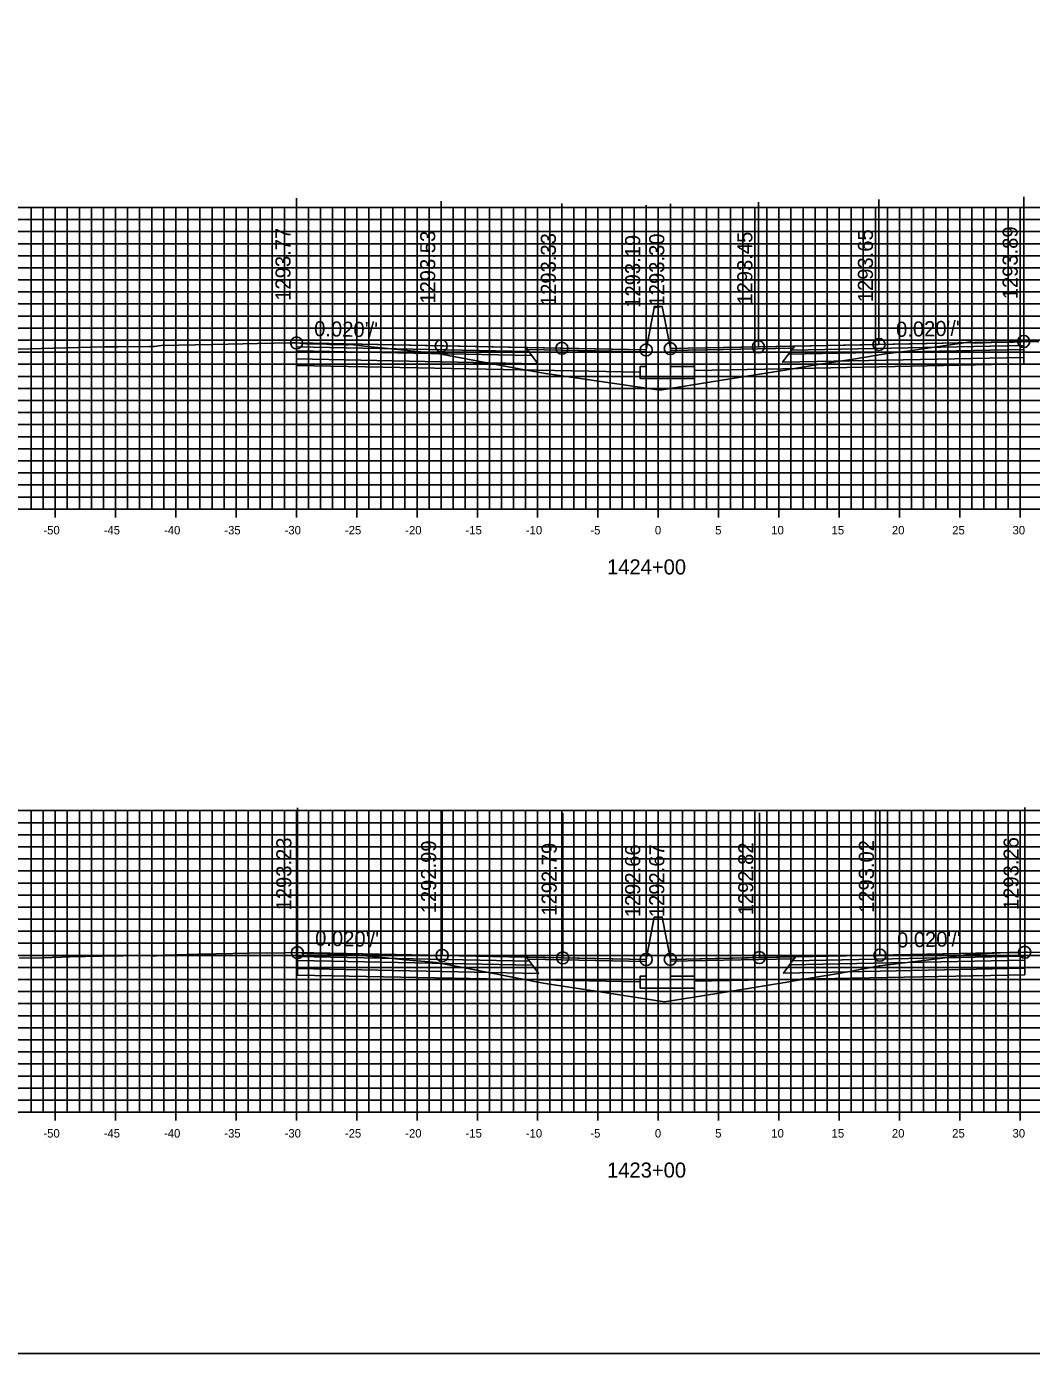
# Model space of a CAD drawing. Extents: x 674939 to 678919, y 750652 to 765176.
# Drawn here: x 678696.2 to 678779.5, y 757822.6 to 757932.6 of the extents above; entities that cross this region are included whole.
import ezdxf

# ---------------------------------------------------------------- set-up
doc = ezdxf.new("R2010")
doc.units = 0
for name, color, linetype in [('R_Alt Surface', 7, 'Continuous'), ('R_Axis', 7, 'Continuous'), ('R_Axis Annot', 7, 'Continuous'), ('R_Exist Surface', 7, 'Continuous'), ('R_Fin Surface', 7, 'Continuous'), ('R_Grid', 7, 'Continuous'), ('R_No Plot', 7, 'Continuous'), ('R_Proposed Road', 7, 'Continuous'), ('R_Xsect Elev', 7, 'Continuous'), ('R_Xsect Slope', 7, 'Continuous')]:
    doc.layers.add(name, color=color, linetype=linetype)

msp = doc.modelspace()

# ---------------------------------------------------------------- linework, layer by layer
for points in [[(678748.2, 757909.24), (678747.53, 757905.74)], [(678748.86, 757909.35), (678748.86, 757909.35), (678748.2, 757909.35), (678748.2, 757909.24)], [(678748.86, 757909.35), (678749.53, 757905.85)], [(678748.2, 757858.71), (678747.53, 757855.21)], [(678748.86, 757858.72), (678748.86, 757858.72), (678748.2, 757858.72), (678748.2, 757858.71)], [(678748.86, 757858.72), (678749.53, 757855.22)]]:
    msp.add_lwpolyline(points)
at = {"layer": 'R_Alt Surface'}
for points in [[(678718.54, 757905.99), (678718.54, 757905.66), (678738.04, 757905.27), (678737.79, 757905.61)], [(678718.54, 757905.66), (678718.54, 757905), (678738.54, 757904.6), (678738.04, 757905.27)], [(678778.83, 757905.78), (678778.83, 757905.12), (678758.83, 757904.72), (678759.33, 757905.39)], [(678778.83, 757906.11), (678778.83, 757905.78), (678759.33, 757905.39), (678759.58, 757905.72)], [(678718.61, 757855.45), (678718.61, 757855.12), (678738.11, 757854.73), (678737.86, 757855.07)], [(678718.61, 757855.12), (678718.61, 757854.46), (678738.61, 757854.06), (678738.11, 757854.73)], [(678778.91, 757855.15), (678778.91, 757854.49), (678758.91, 757854.09), (678759.41, 757854.76)], [(678778.91, 757855.48), (678778.91, 757855.15), (678759.41, 757854.76), (678759.66, 757855.1)]]:
    msp.add_lwpolyline(points, close=True, dxfattribs=at)
for points in [[(678718.54, 757905), (678718.54, 757904.46), (678738.54, 757904.06), (678747.03, 757903.89)], [(678778.83, 757905.12), (678778.83, 757904.58), (678758.83, 757904.18), (678751.53, 757904.03)], [(678718.61, 757854.46), (678718.61, 757853.92), (678738.61, 757853.52), (678747.03, 757853.36)], [(678778.91, 757854.49), (678778.91, 757853.95), (678758.91, 757853.55), (678751.53, 757853.4)]]:
    msp.add_lwpolyline(points, dxfattribs=at)
at = {"layer": 'R_Axis'}
for p, q in [((678598.53, 757892.55), (678898.53, 757892.55)), ((678698.53, 757891.85), (678698.53, 757893.25)), ((678703.53, 757891.85), (678703.53, 757893.25)), ((678708.53, 757891.85), (678708.53, 757893.25)), ((678713.53, 757891.85), (678713.53, 757893.25)), ((678718.53, 757891.85), (678718.53, 757893.25)), ((678723.53, 757891.85), (678723.53, 757893.25)), ((678728.53, 757891.85), (678728.53, 757893.25)), ((678733.53, 757891.85), (678733.53, 757893.25)), ((678738.53, 757891.85), (678738.53, 757893.25)), ((678743.53, 757891.85), (678743.53, 757893.25)), ((678748.53, 757891.85), (678748.53, 757893.25)), ((678753.53, 757891.85), (678753.53, 757893.25)), ((678758.53, 757891.85), (678758.53, 757893.25)), ((678763.53, 757891.85), (678763.53, 757893.25)), ((678768.53, 757891.85), (678768.53, 757893.25)), ((678773.53, 757891.85), (678773.53, 757893.25)), ((678778.53, 757891.85), (678778.53, 757893.25)), ((678698.53, 757841.85), (678698.53, 757843.25)), ((678703.53, 757841.85), (678703.53, 757843.25)), ((678708.53, 757841.85), (678708.53, 757843.25)), ((678713.53, 757841.85), (678713.53, 757843.25)), ((678718.53, 757841.85), (678718.53, 757843.25)), ((678723.53, 757841.85), (678723.53, 757843.25)), ((678728.53, 757841.85), (678728.53, 757843.25)), ((678733.53, 757841.85), (678733.53, 757843.25)), ((678738.53, 757841.85), (678738.53, 757843.25)), ((678743.53, 757841.85), (678743.53, 757843.25)), ((678748.53, 757841.85), (678748.53, 757843.25)), ((678753.53, 757841.85), (678753.53, 757843.25)), ((678758.53, 757841.85), (678758.53, 757843.25)), ((678763.53, 757841.85), (678763.53, 757843.25)), ((678768.53, 757841.85), (678768.53, 757843.25)), ((678773.53, 757841.85), (678773.53, 757843.25)), ((678778.53, 757841.85), (678778.53, 757843.25)), ((678598.53, 757842.55), (678898.53, 757842.55))]:
    msp.add_line(p, q, dxfattribs=at)
at = {"layer": 'R_Exist Surface'}
for points in [[(678695.45, 757905.81), (678697.36, 757905.87), (678702.49, 757905.99), (678703.75, 757906.01), (678706.32, 757906.04), (678706.46, 757906.02), (678706.52, 757906.02), (678706.75, 757906.04), (678707.32, 757906.1), (678710.16, 757906.16), (678712.88, 757906.22), (678715.29, 757906.27), (678718, 757906.32), (678718.52, 757906.32), (678718.52, 757906.32), (678718.54, 757906.32), (678719.09, 757906.27), (678719.37, 757906.25), (678720.37, 757906.25), (678720.72, 757906.25), (678721.29, 757906.2), (678721.81, 757906.18), (678722.66, 757906.16), (678722.77, 757906.17), (678723.02, 757906.18), (678723.05, 757906.19), (678724.16, 757906.06), (678730.22, 757905.45), (678737, 757904.17), (678739.18, 757903.78), (678744.15, 757903.07), (678748.67, 757902.41), (678755.34, 757903.48), (678759.01, 757904.07), (678761.78, 757904.53), (678764.88, 757905.01), (678767.34, 757905.43), (678769.41, 757905.68), (678771.2, 757905.95), (678774.44, 757906.41), (678774.55, 757906.37), (678774.66, 757906.32), (678774.87, 757906.31), (678775.5, 757906.34), (678776.82, 757906.38), (678777.98, 757906.39), (678778.46, 757906.4), (678778.64, 757906.42), (678778.83, 757906.44), (678778.85, 757906.44), (678778.95, 757906.44), (678780.08, 757906.41)], [(678695.56, 757855.32), (678697.56, 757855.36), (678699.74, 757855.42), (678702.36, 757855.48), (678704.17, 757855.5), (678706.29, 757855.53), (678706.54, 757855.51), (678706.69, 757855.5), (678706.91, 757855.52), (678707.66, 757855.58), (678710.4, 757855.64), (678713.27, 757855.7), (678716.01, 757855.75), (678716.13, 757855.74), (678717.49, 757855.76), (678718.49, 757855.8), (678718.61, 757855.78), (678718.62, 757855.78), (678718.92, 757855.76), (678719.41, 757855.72), (678719.72, 757855.71), (678720.34, 757855.71), (678721.1, 757855.68), (678722.46, 757855.62), (678722.82, 757855.61), (678723.18, 757855.63), (678727.56, 757855.19), (678728.85, 757855.08), (678730.14, 757854.96), (678731.43, 757854.71), (678733.19, 757854.37), (678739, 757853.25), (678744.43, 757852.42), (678749.06, 757851.7), (678754.96, 757852.65), (678759.03, 757853.3), (678761.13, 757853.66), (678763.65, 757854.09), (678766.89, 757854.69), (678772.1, 757855.33), (678774.6, 757855.68), (678774.63, 757855.68), (678774.73, 757855.65), (678776.35, 757855.73), (678776.89, 757855.75), (678778.18, 757855.78), (678778.45, 757855.79), (678778.91, 757855.81), (678778.95, 757855.81), (678779.13, 757855.82), (678781.27, 757855.79)]]:
    msp.add_lwpolyline(points, dxfattribs=at)
at = {"layer": 'R_Fin Surface'}
for points in [[(678718.54, 757906.32), (678730.54, 757906.08), (678737.54, 757905.94), (678740.54, 757905.88), (678747.53, 757905.74), (678748.2, 757909.24), (678748.86, 757909.35), (678749.53, 757905.85), (678756.83, 757906), (678759.83, 757906.06), (678766.83, 757906.2), (678778.83, 757906.44)], [(678747.53, 757905.74), (678740.54, 757905.88), (678730.54, 757906.08), (678718.54, 757906.32)], [(678778.83, 757906.44), (678766.83, 757906.2), (678756.83, 757906), (678749.53, 757905.85)], [(678718.61, 757855.78), (678730.61, 757855.54), (678737.61, 757855.4), (678740.61, 757855.34), (678747.53, 757855.21), (678748.2, 757858.71), (678748.86, 757858.72), (678749.53, 757855.22), (678756.91, 757855.37), (678759.91, 757855.43), (678766.91, 757855.57), (678778.91, 757855.81)], [(678747.53, 757855.21), (678740.61, 757855.34), (678730.61, 757855.54), (678718.61, 757855.78)], [(678778.91, 757855.81), (678766.91, 757855.57), (678756.91, 757855.37), (678749.53, 757855.22)]]:
    msp.add_lwpolyline(points, dxfattribs=at)
for points in [[(678718.54, 757906.32), (678718.54, 757905.99), (678737.79, 757905.61), (678737.54, 757905.94)], [(678737.54, 757905.94), (678747.53, 757905.74), (678747.54, 757905.58), (678737.66, 757905.78)], [(678759.71, 757905.9), (678749.53, 757905.69), (678749.53, 757905.85), (678759.83, 757906.06)], [(678778.83, 757906.44), (678778.83, 757906.11), (678759.58, 757905.72), (678759.83, 757906.06)], [(678718.61, 757855.78), (678718.61, 757855.45), (678737.86, 757855.07), (678737.61, 757855.4)], [(678737.61, 757855.4), (678747.53, 757855.21), (678747.54, 757855.05), (678737.73, 757855.24)], [(678759.79, 757855.27), (678749.53, 757855.07), (678749.53, 757855.22), (678759.91, 757855.43)], [(678778.91, 757855.81), (678778.91, 757855.48), (678759.66, 757855.1), (678759.91, 757855.43)]]:
    msp.add_lwpolyline(points, close=True, dxfattribs=at)
at = {"layer": 'R_Grid'}
for p, q in [((678598.53, 757917.55), (678898.53, 757917.55)), ((678598.53, 757916.55), (678898.53, 757916.55)), ((678696.53, 757892.55), (678696.53, 757917.55)), ((678697.53, 757892.55), (678697.53, 757917.55)), ((678698.53, 757892.55), (678698.53, 757917.55)), ((678699.53, 757892.55), (678699.53, 757917.55)), ((678700.53, 757892.55), (678700.53, 757917.55)), ((678701.53, 757892.55), (678701.53, 757917.55)), ((678702.53, 757892.55), (678702.53, 757917.55)), ((678703.53, 757892.55), (678703.53, 757917.55)), ((678704.53, 757892.55), (678704.53, 757917.55)), ((678705.53, 757892.55), (678705.53, 757917.55)), ((678706.53, 757892.55), (678706.53, 757917.55)), ((678707.53, 757892.55), (678707.53, 757917.55)), ((678708.53, 757892.55), (678708.53, 757917.55)), ((678709.53, 757892.55), (678709.53, 757917.55)), ((678710.53, 757892.55), (678710.53, 757917.55)), ((678711.53, 757892.55), (678711.53, 757917.55)), ((678712.53, 757892.55), (678712.53, 757917.55)), ((678713.53, 757892.55), (678713.53, 757917.55)), ((678714.53, 757892.55), (678714.53, 757917.55)), ((678715.53, 757892.55), (678715.53, 757917.55)), ((678716.53, 757892.55), (678716.53, 757917.55)), ((678717.53, 757892.55), (678717.53, 757917.55)), ((678718.53, 757892.55), (678718.53, 757917.55)), ((678719.53, 757892.55), (678719.53, 757917.55)), ((678720.53, 757892.55), (678720.53, 757917.55)), ((678721.53, 757892.55), (678721.53, 757917.55)), ((678722.53, 757892.55), (678722.53, 757917.55)), ((678723.53, 757892.55), (678723.53, 757917.55)), ((678724.53, 757892.55), (678724.53, 757917.55)), ((678725.53, 757892.55), (678725.53, 757917.55)), ((678726.53, 757892.55), (678726.53, 757917.55)), ((678727.53, 757892.55), (678727.53, 757917.55)), ((678728.53, 757892.55), (678728.53, 757917.55)), ((678729.53, 757892.55), (678729.53, 757917.55)), ((678730.53, 757892.55), (678730.53, 757917.55)), ((678731.53, 757892.55), (678731.53, 757917.55)), ((678732.53, 757892.55), (678732.53, 757917.55)), ((678733.53, 757892.55), (678733.53, 757917.55)), ((678734.53, 757892.55), (678734.53, 757917.55)), ((678735.53, 757892.55), (678735.53, 757917.55)), ((678736.53, 757892.55), (678736.53, 757917.55)), ((678737.53, 757892.55), (678737.53, 757917.55)), ((678738.53, 757892.55), (678738.53, 757917.55)), ((678739.53, 757892.55), (678739.53, 757917.55)), ((678740.53, 757892.55), (678740.53, 757917.55)), ((678741.53, 757892.55), (678741.53, 757917.55)), ((678742.53, 757892.55), (678742.53, 757917.55)), ((678743.53, 757892.55), (678743.53, 757917.55)), ((678744.53, 757892.55), (678744.53, 757917.55)), ((678745.53, 757892.55), (678745.53, 757917.55)), ((678746.53, 757892.55), (678746.53, 757917.55)), ((678747.53, 757892.55), (678747.53, 757917.55)), ((678748.53, 757892.55), (678748.53, 757917.55)), ((678749.53, 757892.55), (678749.53, 757917.55)), ((678750.53, 757892.55), (678750.53, 757917.55)), ((678751.53, 757892.55), (678751.53, 757917.55)), ((678752.53, 757892.55), (678752.53, 757917.55)), ((678753.53, 757892.55), (678753.53, 757917.55)), ((678754.53, 757892.55), (678754.53, 757917.55)), ((678755.53, 757892.55), (678755.53, 757917.55)), ((678756.53, 757892.55), (678756.53, 757917.55)), ((678757.53, 757892.55), (678757.53, 757917.55)), ((678758.53, 757892.55), (678758.53, 757917.55)), ((678759.53, 757892.55), (678759.53, 757917.55)), ((678760.53, 757892.55), (678760.53, 757917.55)), ((678761.53, 757892.55), (678761.53, 757917.55)), ((678762.53, 757892.55), (678762.53, 757917.55)), ((678763.53, 757892.55), (678763.53, 757917.55)), ((678764.53, 757892.55), (678764.53, 757917.55)), ((678765.53, 757892.55), (678765.53, 757917.55)), ((678766.53, 757892.55), (678766.53, 757917.55)), ((678767.53, 757892.55), (678767.53, 757917.55)), ((678768.53, 757892.55), (678768.53, 757917.55)), ((678769.53, 757892.55), (678769.53, 757917.55)), ((678770.53, 757892.55), (678770.53, 757917.55)), ((678771.53, 757892.55), (678771.53, 757917.55)), ((678772.53, 757892.55), (678772.53, 757917.55)), ((678773.53, 757892.55), (678773.53, 757917.55)), ((678774.53, 757892.55), (678774.53, 757917.55)), ((678775.53, 757892.55), (678775.53, 757917.55)), ((678776.53, 757892.55), (678776.53, 757917.55)), ((678777.53, 757892.55), (678777.53, 757917.55)), ((678778.53, 757892.55), (678778.53, 757917.55)), ((678598.53, 757915.55), (678898.53, 757915.55)), ((678598.53, 757914.55), (678898.53, 757914.55)), ((678598.53, 757913.55), (678898.53, 757913.55)), ((678598.53, 757912.55), (678898.53, 757912.55)), ((678598.53, 757911.55), (678898.53, 757911.55)), ((678598.53, 757910.55), (678898.53, 757910.55)), ((678598.53, 757909.55), (678898.53, 757909.55)), ((678598.53, 757908.55), (678898.53, 757908.55)), ((678598.53, 757907.55), (678898.53, 757907.55)), ((678598.53, 757906.55), (678898.53, 757906.55)), ((678598.53, 757905.55), (678898.53, 757905.55)), ((678598.53, 757904.55), (678898.53, 757904.55)), ((678598.53, 757903.55), (678898.53, 757903.55)), ((678598.53, 757902.55), (678898.53, 757902.55)), ((678598.53, 757901.55), (678898.53, 757901.55)), ((678598.53, 757900.55), (678898.53, 757900.55)), ((678598.53, 757899.55), (678898.53, 757899.55)), ((678598.53, 757898.55), (678898.53, 757898.55)), ((678598.53, 757897.55), (678898.53, 757897.55)), ((678598.53, 757896.55), (678898.53, 757896.55)), ((678598.53, 757895.55), (678898.53, 757895.55)), ((678598.53, 757894.55), (678898.53, 757894.55)), ((678598.53, 757893.55), (678898.53, 757893.55)), ((678598.53, 757892.55), (678898.53, 757892.55)), ((678598.53, 757867.55), (678898.53, 757867.55)), ((678696.53, 757842.55), (678696.53, 757867.55)), ((678697.53, 757842.55), (678697.53, 757867.55)), ((678698.53, 757842.55), (678698.53, 757867.55)), ((678699.53, 757842.55), (678699.53, 757867.55)), ((678700.53, 757842.55), (678700.53, 757867.55)), ((678701.53, 757842.55), (678701.53, 757867.55)), ((678702.53, 757842.55), (678702.53, 757867.55)), ((678703.53, 757842.55), (678703.53, 757867.55)), ((678704.53, 757842.55), (678704.53, 757867.55)), ((678705.53, 757842.55), (678705.53, 757867.55)), ((678706.53, 757842.55), (678706.53, 757867.55)), ((678707.53, 757842.55), (678707.53, 757867.55)), ((678708.53, 757842.55), (678708.53, 757867.55)), ((678709.53, 757842.55), (678709.53, 757867.55)), ((678710.53, 757842.55), (678710.53, 757867.55)), ((678711.53, 757842.55), (678711.53, 757867.55)), ((678712.53, 757842.55), (678712.53, 757867.55)), ((678713.53, 757842.55), (678713.53, 757867.55)), ((678714.53, 757842.55), (678714.53, 757867.55)), ((678715.53, 757842.55), (678715.53, 757867.55)), ((678716.53, 757842.55), (678716.53, 757867.55)), ((678717.53, 757842.55), (678717.53, 757867.55)), ((678718.53, 757842.55), (678718.53, 757867.55)), ((678719.53, 757842.55), (678719.53, 757867.55)), ((678720.53, 757842.55), (678720.53, 757867.55)), ((678721.53, 757842.55), (678721.53, 757867.55)), ((678722.53, 757842.55), (678722.53, 757867.55)), ((678723.53, 757842.55), (678723.53, 757867.55)), ((678724.53, 757842.55), (678724.53, 757867.55)), ((678725.53, 757842.55), (678725.53, 757867.55)), ((678726.53, 757842.55), (678726.53, 757867.55)), ((678727.53, 757842.55), (678727.53, 757867.55)), ((678728.53, 757842.55), (678728.53, 757867.55)), ((678729.53, 757842.55), (678729.53, 757867.55)), ((678730.53, 757842.55), (678730.53, 757867.55)), ((678731.53, 757842.55), (678731.53, 757867.55)), ((678732.53, 757842.55), (678732.53, 757867.55)), ((678733.53, 757842.55), (678733.53, 757867.55)), ((678734.53, 757842.55), (678734.53, 757867.55)), ((678735.53, 757842.55), (678735.53, 757867.55)), ((678736.53, 757842.55), (678736.53, 757867.55)), ((678737.53, 757842.55), (678737.53, 757867.55)), ((678738.53, 757842.55), (678738.53, 757867.55)), ((678739.53, 757842.55), (678739.53, 757867.55)), ((678740.53, 757842.55), (678740.53, 757867.55)), ((678741.53, 757842.55), (678741.53, 757867.55)), ((678742.53, 757842.55), (678742.53, 757867.55)), ((678743.53, 757842.55), (678743.53, 757867.55)), ((678744.53, 757842.55), (678744.53, 757867.55)), ((678745.53, 757842.55), (678745.53, 757867.55)), ((678746.53, 757842.55), (678746.53, 757867.55)), ((678747.53, 757842.55), (678747.53, 757867.55)), ((678748.53, 757842.55), (678748.53, 757867.55)), ((678749.53, 757842.55), (678749.53, 757867.55)), ((678750.53, 757842.55), (678750.53, 757867.55)), ((678751.53, 757842.55), (678751.53, 757867.55)), ((678752.53, 757842.55), (678752.53, 757867.55)), ((678753.53, 757842.55), (678753.53, 757867.55)), ((678754.53, 757842.55), (678754.53, 757867.55)), ((678755.53, 757842.55), (678755.53, 757867.55)), ((678756.53, 757842.55), (678756.53, 757867.55)), ((678757.53, 757842.55), (678757.53, 757867.55)), ((678758.53, 757842.55), (678758.53, 757867.55)), ((678759.53, 757842.55), (678759.53, 757867.55)), ((678760.53, 757842.55), (678760.53, 757867.55)), ((678761.53, 757842.55), (678761.53, 757867.55)), ((678762.53, 757842.55), (678762.53, 757867.55)), ((678763.53, 757842.55), (678763.53, 757867.55)), ((678764.53, 757842.55), (678764.53, 757867.55)), ((678765.53, 757842.55), (678765.53, 757867.55)), ((678766.53, 757842.55), (678766.53, 757867.55)), ((678767.53, 757842.55), (678767.53, 757867.55)), ((678768.53, 757842.55), (678768.53, 757867.55)), ((678769.53, 757842.55), (678769.53, 757867.55)), ((678770.53, 757842.55), (678770.53, 757867.55)), ((678771.53, 757842.55), (678771.53, 757867.55)), ((678772.53, 757842.55), (678772.53, 757867.55)), ((678773.53, 757842.55), (678773.53, 757867.55)), ((678774.53, 757842.55), (678774.53, 757867.55)), ((678775.53, 757842.55), (678775.53, 757867.55)), ((678776.53, 757842.55), (678776.53, 757867.55)), ((678777.53, 757842.55), (678777.53, 757867.55)), ((678778.53, 757842.55), (678778.53, 757867.55)), ((678598.53, 757866.55), (678898.53, 757866.55)), ((678598.53, 757865.55), (678898.53, 757865.55)), ((678598.53, 757864.55), (678898.53, 757864.55)), ((678598.53, 757863.55), (678898.53, 757863.55)), ((678598.53, 757862.55), (678898.53, 757862.55)), ((678598.53, 757861.55), (678898.53, 757861.55)), ((678598.53, 757860.55), (678898.53, 757860.55)), ((678598.53, 757859.55), (678898.53, 757859.55)), ((678598.53, 757858.55), (678898.53, 757858.55)), ((678598.53, 757857.55), (678898.53, 757857.55)), ((678598.53, 757856.55), (678898.53, 757856.55)), ((678598.53, 757855.55), (678898.53, 757855.55)), ((678598.53, 757854.55), (678898.53, 757854.55)), ((678598.53, 757853.55), (678898.53, 757853.55)), ((678598.53, 757852.55), (678898.53, 757852.55)), ((678598.53, 757851.55), (678898.53, 757851.55)), ((678598.53, 757850.55), (678898.53, 757850.55)), ((678598.53, 757849.55), (678898.53, 757849.55)), ((678598.53, 757848.55), (678898.53, 757848.55)), ((678598.53, 757847.55), (678898.53, 757847.55)), ((678598.53, 757846.55), (678898.53, 757846.55)), ((678598.53, 757845.55), (678898.53, 757845.55)), ((678598.53, 757844.55), (678898.53, 757844.55)), ((678598.53, 757843.55), (678898.53, 757843.55)), ((678598.53, 757842.55), (678898.53, 757842.55))]:
    msp.add_line(p, q, dxfattribs=at)
at = {"layer": 'R_No Plot'}
msp.add_lwpolyline([(678578.53, 757822.55), (678918.53, 757822.55), (678918.53, 758042.55), (678578.53, 758042.55)], close=True, dxfattribs=at)
for centre in [(678718.54, 757906.32), (678766.83, 757906.2), (678778.83, 757906.44), (678730.54, 757906.08), (678740.54, 757905.88), (678747.53, 757905.74), (678749.53, 757905.85), (678756.83, 757906), (678718.61, 757855.78), (678730.61, 757855.54), (678766.91, 757855.57), (678778.91, 757855.81), (678740.61, 757855.34), (678747.53, 757855.21), (678749.53, 757855.22), (678756.91, 757855.37)]:
    msp.add_circle(centre, 0.5, dxfattribs=at)
at = {"layer": 'R_Proposed Road'}
for points in [[(678747.53, 757905.74), (678747.53, 757904.37), (678747.03, 757904.37), (678747.03, 757903.37), (678751.53, 757903.37), (678751.53, 757904.37), (678749.53, 757904.37), (678749.53, 757905.85)], [(678747.53, 757855.21), (678747.53, 757853.83), (678747.03, 757853.83), (678747.03, 757852.83), (678751.53, 757852.83), (678751.53, 757853.83), (678749.53, 757853.83), (678749.53, 757855.22)]]:
    msp.add_lwpolyline(points, dxfattribs=at)
at = {"layer": 'R_Xsect Elev'}
for p, q in [((678718.54, 757906.32), (678718.54, 757918.32)), ((678730.54, 757906.08), (678730.54, 757918.08)), ((678740.54, 757905.88), (678740.54, 757917.88)), ((678747.53, 757905.74), (678747.53, 757917.74)), ((678749.53, 757905.85), (678749.53, 757917.85)), ((678756.83, 757906), (678756.83, 757918)), ((678766.83, 757906.2), (678766.83, 757918.2)), ((678778.83, 757906.44), (678778.83, 757918.44)), ((678718.61, 757855.78), (678718.61, 757867.78)), ((678730.61, 757855.54), (678730.61, 757867.54)), ((678740.61, 757855.34), (678740.61, 757867.34)), ((678747.53, 757855.21), (678747.53, 757867.21)), ((678749.53, 757855.22), (678749.53, 757867.22)), ((678756.91, 757855.37), (678756.91, 757867.37)), ((678766.91, 757855.57), (678766.91, 757867.57)), ((678778.91, 757855.81), (678778.91, 757867.81))]:
    msp.add_line(p, q, dxfattribs=at)

# ---------------------------------------------------------------- texts
at = {"layer": 'R_Axis Annot'}
for s, height, p in [('-50', 0.7, (678697.55, 757890.45)), ('-45', 0.7, (678702.55, 757890.45)), ('-40', 0.7, (678707.55, 757890.45)), ('-35', 0.7, (678712.55, 757890.45)), ('-30', 0.7, (678717.55, 757890.45)), ('-25', 0.7, (678722.55, 757890.45)), ('-20', 0.7, (678727.55, 757890.45)), ('-15', 0.7, (678732.55, 757890.45)), ('-10', 0.7, (678737.55, 757890.45)), ('-5', 0.7, (678742.9, 757890.45)), ('0', 0.7, (678748.25, 757890.45)), ('5', 0.7, (678753.25, 757890.45)), ('10', 0.7, (678757.9, 757890.45)), ('15', 0.7, (678762.9, 757890.45)), ('20', 0.7, (678767.9, 757890.45)), ('25', 0.7, (678772.9, 757890.45)), ('30', 0.7, (678777.9, 757890.45)), ('1424+00', 1.25, (678744.28, 757887.13)), ('-50', 0.7, (678697.55, 757840.45)), ('-45', 0.7, (678702.55, 757840.45)), ('-40', 0.7, (678707.55, 757840.45)), ('-35', 0.7, (678712.55, 757840.45)), ('-30', 0.7, (678717.55, 757840.45)), ('-25', 0.7, (678722.55, 757840.45)), ('-20', 0.7, (678727.55, 757840.45)), ('-15', 0.7, (678732.55, 757840.45)), ('-10', 0.7, (678737.55, 757840.45)), ('-5', 0.7, (678742.9, 757840.45)), ('0', 0.7, (678748.25, 757840.45)), ('5', 0.7, (678753.25, 757840.45)), ('10', 0.7, (678757.9, 757840.45)), ('15', 0.7, (678762.9, 757840.45)), ('20', 0.7, (678767.9, 757840.45)), ('25', 0.7, (678772.9, 757840.45)), ('30', 0.7, (678777.9, 757840.45)), ('1423+00', 1.25, (678744.28, 757837.13))]:
    msp.add_text(s, height=height, dxfattribs=at).set_placement(p)
at = {"layer": 'R_Xsect Elev'}
for s, p in [('1293.77', (678718.04, 757909.82)), ('1293.53', (678730.04, 757909.58)), ('1293.45', (678756.33, 757909.5)), ('1293.65', (678766.33, 757909.7)), ('1293.89', (678778.33, 757909.94)), ('1293.33', (678740.04, 757909.38)), ('1293.19', (678747.03, 757909.24)), ('1293.30', (678749.03, 757909.35)), ('1293.23', (678718.11, 757859.28)), ('1292.99', (678730.11, 757859.04)), ('1292.79', (678740.11, 757858.84)), ('1292.82', (678756.41, 757858.87)), ('1293.02', (678766.41, 757859.07)), ('1293.26', (678778.41, 757859.31)), ('1292.66', (678747.03, 757858.71)), ('1292.67', (678749.03, 757858.72))]:
    msp.add_text(s, height=1.25, rotation=90, dxfattribs=at).set_placement(p)
at = {"layer": 'R_Xsect Slope'}
for rotation, p in [(358.8542, (678719.99, 757906.89)), (1.1458, (678768.26, 757906.82)), (358.8542, (678720.07, 757856.36)), (1.1458, (678768.34, 757856.2))]:
    msp.add_text("0.020'/'", height=1.25, rotation=rotation, dxfattribs=at).set_placement(p)

doc.saveas('drawing.dxf')
